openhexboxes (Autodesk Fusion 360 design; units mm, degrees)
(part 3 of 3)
sketch "Skizze22" plane through (0, 0, 0.3) normal (0, 0, -1) x axis (-1, 0, 0)
  line L1 (62.5498, -172.3991) -> (57.5498, -172.3991)
  line L2 (62.5498, -177.3991) -> (62.5498, -172.3991)
  line L3 (57.5498, -177.3991) -> (62.5498, -177.3991)
  line L4 (57.5498, -172.3991) -> (57.5498, -177.3991)
  line L5 (22.7498, -207.1991) -> (22.7498, -212.1991)
  line L6 (22.7498, -212.1991) -> (27.7498, -212.1991)
  line L7 (27.7498, -212.1991) -> (27.7498, -207.1991)
  line L8 (27.7498, -207.1991) -> (22.7498, -207.1991)
  line L9 (28.5498, -207.1991) -> (28.5498, -212.1991)
  line L10 (28.5498, -212.1991) -> (33.5498, -212.1991)
  line L11 (33.5498, -212.1991) -> (33.5498, -207.1991)
  line L12 (33.5498, -207.1991) -> (28.5498, -207.1991)
  line L13 (34.3498, -207.1991) -> (34.3498, -212.1991)
  line L14 (34.3498, -212.1991) -> (39.3498, -212.1991)
  line L15 (39.3498, -212.1991) -> (39.3498, -207.1991)
  line L16 (39.3498, -207.1991) -> (34.3498, -207.1991)
  line L17 (40.1498, -207.1991) -> (40.1498, -212.1991)
  line L18 (40.1498, -212.1991) -> (45.1498, -212.1991)
  line L19 (45.1498, -212.1991) -> (45.1498, -207.1991)
  line L20 (45.1498, -207.1991) -> (40.1498, -207.1991)
  line L21 (45.9498, -207.1991) -> (45.9498, -212.1991)
  line L22 (45.9498, -212.1991) -> (50.9498, -212.1991)
  line L23 (50.9498, -212.1991) -> (50.9498, -207.1991)
  line L24 (50.9498, -207.1991) -> (45.9498, -207.1991)
  line L25 (51.7498, -207.1991) -> (51.7498, -212.1991)
  line L26 (51.7498, -212.1991) -> (56.7498, -212.1991)
  line L27 (56.7498, -212.1991) -> (56.7498, -207.1991)
  line L28 (56.7498, -207.1991) -> (51.7498, -207.1991)
  line L29 (57.5498, -207.1991) -> (57.5498, -212.1991)
  line L30 (57.5498, -212.1991) -> (62.5498, -212.1991)
  line L31 (62.5498, -212.1991) -> (62.5498, -207.1991)
  line L32 (62.5498, -207.1991) -> (57.5498, -207.1991)
  line L33 (63.3498, -207.1991) -> (63.3498, -212.1991)
  line L34 (63.3498, -212.1991) -> (68.3498, -212.1991)
  line L35 (68.3498, -212.1991) -> (68.3498, -207.1991)
  line L36 (68.3498, -207.1991) -> (63.3498, -207.1991)
  line L37 (69.1498, -207.1991) -> (69.1498, -212.1991)
  line L38 (69.1498, -212.1991) -> (74.1498, -212.1991)
  line L39 (74.1498, -212.1991) -> (74.1498, -207.1991)
  line L40 (74.1498, -207.1991) -> (69.1498, -207.1991)
  line L41 (74.9498, -207.1991) -> (74.9498, -212.1991)
  line L42 (74.9498, -212.1991) -> (79.9498, -212.1991)
  line L43 (79.9498, -212.1991) -> (79.9498, -207.1991)
  line L44 (79.9498, -207.1991) -> (74.9498, -207.1991)
  line L45 (80.7498, -207.1991) -> (80.7498, -212.1991)
  line L46 (80.7498, -212.1991) -> (85.7498, -212.1991)
  line L47 (85.7498, -212.1991) -> (85.7498, -207.1991)
  line L48 (85.7498, -207.1991) -> (80.7498, -207.1991)
  line L49 (86.5498, -207.1991) -> (86.5498, -212.1991)
  line L50 (86.5498, -212.1991) -> (91.5498, -212.1991)
  line L51 (91.5498, -212.1991) -> (91.5498, -207.1991)
  line L52 (91.5498, -207.1991) -> (86.5498, -207.1991)
  line L53 (92.3498, -207.1991) -> (92.3498, -212.1991)
  line L54 (92.3498, -212.1991) -> (97.3498, -212.1991)
  line L55 (97.3498, -212.1991) -> (97.3498, -207.1991)
  line L56 (97.3498, -207.1991) -> (92.3498, -207.1991)
  line L57 (98.1498, -207.1991) -> (98.1498, -212.1991)
  line L58 (98.1498, -212.1991) -> (103.1498, -212.1991)
  line L59 (103.1498, -212.1991) -> (103.1498, -207.1991)
  line L60 (103.1498, -207.1991) -> (98.1498, -207.1991)
  line L61 (22.7498, -201.3991) -> (22.7498, -206.3991)
  line L62 (22.7498, -206.3991) -> (27.7498, -206.3991)
  line L63 (27.7498, -206.3991) -> (27.7498, -201.3991)
  line L64 (27.7498, -201.3991) -> (22.7498, -201.3991)
  line L65 (28.5498, -201.3991) -> (28.5498, -206.3991)
  line L66 (28.5498, -206.3991) -> (33.5498, -206.3991)
  line L67 (33.5498, -206.3991) -> (33.5498, -201.3991)
  line L68 (33.5498, -201.3991) -> (28.5498, -201.3991)
  line L69 (34.3498, -201.3991) -> (34.3498, -206.3991)
  line L70 (34.3498, -206.3991) -> (39.3498, -206.3991)
  line L71 (39.3498, -206.3991) -> (39.3498, -201.3991)
  line L72 (39.3498, -201.3991) -> (34.3498, -201.3991)
  line L73 (40.1498, -201.3991) -> (40.1498, -206.3991)
  line L74 (40.1498, -206.3991) -> (45.1498, -206.3991)
  line L75 (45.1498, -206.3991) -> (45.1498, -201.3991)
  line L76 (45.1498, -201.3991) -> (40.1498, -201.3991)
  line L77 (45.9498, -201.3991) -> (45.9498, -206.3991)
  line L78 (45.9498, -206.3991) -> (50.9498, -206.3991)
  line L79 (50.9498, -206.3991) -> (50.9498, -201.3991)
  line L80 (50.9498, -201.3991) -> (45.9498, -201.3991)
  line L81 (51.7498, -201.3991) -> (51.7498, -206.3991)
  line L82 (51.7498, -206.3991) -> (56.7498, -206.3991)
  line L83 (56.7498, -206.3991) -> (56.7498, -201.3991)
  line L84 (56.7498, -201.3991) -> (51.7498, -201.3991)
  line L85 (57.5498, -201.3991) -> (57.5498, -206.3991)
  line L86 (57.5498, -206.3991) -> (62.5498, -206.3991)
  line L87 (62.5498, -206.3991) -> (62.5498, -201.3991)
  line L88 (62.5498, -201.3991) -> (57.5498, -201.3991)
  line L89 (63.3498, -201.3991) -> (63.3498, -206.3991)
  line L90 (63.3498, -206.3991) -> (68.3498, -206.3991)
  line L91 (68.3498, -206.3991) -> (68.3498, -201.3991)
  line L92 (68.3498, -201.3991) -> (63.3498, -201.3991)
  line L93 (69.1498, -201.3991) -> (69.1498, -206.3991)
  line L94 (69.1498, -206.3991) -> (74.1498, -206.3991)
  line L95 (74.1498, -206.3991) -> (74.1498, -201.3991)
  line L96 (74.1498, -201.3991) -> (69.1498, -201.3991)
  line L97 (74.9498, -201.3991) -> (74.9498, -206.3991)
  line L98 (74.9498, -206.3991) -> (79.9498, -206.3991)
  line L99 (79.9498, -206.3991) -> (79.9498, -201.3991)
  line L100 (79.9498, -201.3991) -> (74.9498, -201.3991)
  line L101 (80.7498, -201.3991) -> (80.7498, -206.3991)
  line L102 (80.7498, -206.3991) -> (85.7498, -206.3991)
  line L103 (85.7498, -206.3991) -> (85.7498, -201.3991)
  line L104 (85.7498, -201.3991) -> (80.7498, -201.3991)
  line L105 (86.5498, -201.3991) -> (86.5498, -206.3991)
  line L106 (86.5498, -206.3991) -> (91.5498, -206.3991)
  line L107 (91.5498, -206.3991) -> (91.5498, -201.3991)
  line L108 (91.5498, -201.3991) -> (86.5498, -201.3991)
  line L109 (92.3498, -201.3991) -> (92.3498, -206.3991)
  line L110 (92.3498, -206.3991) -> (97.3498, -206.3991)
  line L111 (97.3498, -206.3991) -> (97.3498, -201.3991)
  line L112 (97.3498, -201.3991) -> (92.3498, -201.3991)
  line L113 (98.1498, -201.3991) -> (98.1498, -206.3991)
  line L114 (98.1498, -206.3991) -> (103.1498, -206.3991)
  line L115 (103.1498, -206.3991) -> (103.1498, -201.3991)
  line L116 (103.1498, -201.3991) -> (98.1498, -201.3991)
  line L117 (22.7498, -195.5991) -> (22.7498, -200.5991)
  line L118 (22.7498, -200.5991) -> (27.7498, -200.5991)
  line L119 (27.7498, -200.5991) -> (27.7498, -195.5991)
  line L120 (27.7498, -195.5991) -> (22.7498, -195.5991)
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  point P2 (57.5498, -172.3991)
  point P3 (62.5498, -172.3991)
  point P5 (57.5498, -177.3991)
  dimension "d102" distance P2 P3 = 5
  dimension "d103" distance P2 P5 = 5
  dimension "d108" distance = 4.3915
  dimension "d106" R-Pattern1-uDistance = 5.8
  dimension "d107" R-Pattern1-vDistance = 5.8
sketch "Skizze23"
extrude "Extrusion19" new body sketch "Skizze22" along normal blind 0.3 bodies "small parts"
extrude "Extrusion20" of existing geometry blind 0.3
copy_paste_bodies "Körper kopieren/einfügen8"
move "Verschieben9"
combine "Kombinieren2" bodies "small parts"
sketch "Skizze24" plane through (-57.5498, 0, 0) normal (-1, 0, 0) x axis (0, 0, 1)
  line L1 (0.3, -178.1991) -> (0.3, -183.1991)
  line L2 (0, -178.1991) -> (0.3, -178.1991)
  line L3 (0, -183.1991) -> (0, -178.1991)
  line L4 (0.3, -183.1991) -> (0, -183.1991)
copy_paste_bodies "Körper kopieren/einfügen7"
move "Verschieben8"
copy_paste_bodies "Körper kopieren/einfügen9"
move "Verschieben10"
copy_paste_bodies "Körper kopieren/einfügen10"
move "Verschieben11"
extrude "Extrusion21" of existing geometry blind 9 second side blind 0.3 bodies "grit_for_easy_detach_substraction body"
extrude "Extrusion22" new body of existing geometry blind -0.3
move "Verschieben12"
combine "Kombinieren3"
copy_paste_bodies "Körper kopieren/einfügen11"
move "Verschieben13"
combine "Kombinieren4" bodies "grit_for_easy_detach_substraction body (1)"
copy_paste_bodies "Körper kopieren/einfügen12"
move "Verschieben14"
extrude "Extrusion23" of existing geometry blind -20
sketch "Skizze25" plane through (0, 0, 10) normal (0, 0, 1) x axis (1, 0, 0)
  line L1 (-23.6181, -323.2077) -> (-22.5788, -323.2077)
  line L2 (-20.4382, -315) -> (-24.3975, -321.8577)
  line L3 (-24.3975, -308.1423) -> (-20.4382, -315)
  line L4 (-25.7831, -309.0423) -> (-25.2635, -308.1423)
  line L5 (-33.342, -298.65) -> (-27.342, -309.0423)
  line L6 (-28.0592, -297.3) -> (-32.5626, -297.3)
  line L7 (-33.6262, -286.1577) -> (-27.6262, -296.55)
  line L8 (-35.0119, -287.0577) -> (-34.4922, -286.1577)
  line L9 (-40.53, -280.2) -> (-36.5707, -287.0577)
  line L10 (-48.4486, -280.2) -> (-40.53, -280.2)
  line L11 (-48.362, -281.85) -> (-48.8816, -280.95)
  line L12 (-61.1414, -283.2) -> (-49.1414, -283.2)
  line L13 (-59.6692, -277.95) -> (-61.9208, -281.85)
  line L14 (-72.1022, -277.2) -> (-60.1022, -277.2)
  line L15 (-72.0156, -278.85) -> (-72.5352, -277.95)
  line L16 (-80.7136, -280.2) -> (-72.795, -280.2)
  line L17 (-84.6729, -287.0577) -> (-80.7136, -280.2)
  line L18 (-83.2006, -287.8077) -> (-84.2398, -287.8077)
  line L19 (-88.4212, -299.55) -> (-82.4212, -289.1577)
  line L20 (-92.2317, -295.65) -> (-89.98, -299.55)
  line L21 (-99.0977, -306.0423) -> (-93.0977, -295.65)
  line L22 (-97.6255, -306.7923) -> (-98.6647, -306.7923)
  line L23 (-100.8054, -315) -> (-96.8461, -308.1423)
  line L24 (-96.8461, -321.8577) -> (-100.8054, -315)
  line L25 (-95.4604, -320.9577) -> (-95.98, -321.8577)
  line L26 (-87.9016, -331.35) -> (-93.9016, -320.9577)
  line L27 (-93.1843, -332.7) -> (-88.681, -332.7)
  line L28 (-87.6173, -343.8423) -> (-93.6173, -333.45)
  line L29 (-86.2317, -342.9423) -> (-86.7513, -343.8423)
  line L30 (-80.7136, -349.8) -> (-84.6729, -342.9423)
  line L31 (-72.795, -349.8) -> (-80.7136, -349.8)
  line L32 (-72.8816, -348.15) -> (-72.362, -349.05)
  line L33 (-60.1022, -346.8) -> (-72.1022, -346.8)
  line L34 (-61.5744, -352.05) -> (-59.3227, -348.15)
  line L35 (-49.1414, -352.8) -> (-61.1414, -352.8)
  line L36 (-49.228, -351.15) -> (-48.7084, -352.05)
  line L37 (-40.53, -349.8) -> (-48.4486, -349.8)
  line L38 (-36.5707, -342.9423) -> (-40.53, -349.8)
  line L39 (-38.0429, -342.1923) -> (-37.0037, -342.1923)
  line L40 (-32.8224, -330.45) -> (-38.8224, -340.8423)
  line L41 (-29.0119, -334.35) -> (-31.2635, -330.45)
  line L42 (-22.1458, -323.9577) -> (-28.1458, -334.35)
  line L43 (-61.1414, -352.8) -> (-49.1414, -352.8)
  line L44 (-93.0977, -295.65) -> (-99.0977, -306.0423)
  line L45 (-89.98, -299.55) -> (-92.2317, -295.65)
  line L46 (-82.4212, -289.1577) -> (-88.4212, -299.55)
  line L47 (-84.2398, -287.8077) -> (-83.2006, -287.8077)
  line L48 (-80.7136, -280.2) -> (-84.6729, -287.0577)
  line L49 (-72.795, -280.2) -> (-80.7136, -280.2)
  line L50 (-72.5352, -277.95) -> (-72.0156, -278.85)
  line L51 (-60.1022, -277.2) -> (-72.1022, -277.2)
  line L52 (-61.9208, -281.85) -> (-59.6692, -277.95)
  line L53 (-49.1414, -283.2) -> (-61.1414, -283.2)
  line L54 (-48.8816, -280.95) -> (-48.362, -281.85)
  line L55 (-40.53, -280.2) -> (-48.4486, -280.2)
  line L56 (-36.5707, -287.0577) -> (-40.53, -280.2)
  line L57 (-34.4922, -286.1577) -> (-35.0119, -287.0577)
  line L58 (-27.6262, -296.55) -> (-33.6262, -286.1577)
  line L59 (-32.5626, -297.3) -> (-28.0592, -297.3)
  line L60 (-27.342, -309.0423) -> (-33.342, -298.65)
  line L61 (-25.2635, -308.1423) -> (-25.7831, -309.0423)
  line L62 (-20.4382, -315) -> (-24.3975, -308.1423)
  line L63 (-24.3975, -321.8577) -> (-20.4382, -315)
  line L64 (-22.5788, -323.2077) -> (-23.6181, -323.2077)
  line L65 (-28.1458, -334.35) -> (-22.1458, -323.9577)
  line L66 (-31.2635, -330.45) -> (-29.0119, -334.35)
  line L67 (-38.8224, -340.8423) -> (-32.8224, -330.45)
  line L68 (-37.0037, -342.1923) -> (-38.0429, -342.1923)
  line L69 (-40.53, -349.8) -> (-36.5707, -342.9423)
  line L70 (-48.4486, -349.8) -> (-40.53, -349.8)
  line L71 (-48.7084, -352.05) -> (-49.228, -351.15)
  line L72 (-61.1414, -352.8) -> (-49.1414, -352.8)
  line L73 (-59.3227, -348.15) -> (-61.5744, -352.05)
  line L74 (-72.1022, -346.8) -> (-60.1022, -346.8)
  line L75 (-72.362, -349.05) -> (-72.8816, -348.15)
  line L76 (-80.7136, -349.8) -> (-72.795, -349.8)
  line L77 (-84.6729, -342.9423) -> (-80.7136, -349.8)
  line L78 (-86.7513, -343.8423) -> (-86.2317, -342.9423)
  line L79 (-93.6173, -333.45) -> (-87.6173, -343.8423)
  line L80 (-88.681, -332.7) -> (-93.1843, -332.7)
  line L81 (-93.9016, -320.9577) -> (-87.9016, -331.35)
  line L82 (-95.98, -321.8577) -> (-95.4604, -320.9577)
  line L83 (-100.8054, -315) -> (-96.8461, -321.8577)
  line L84 (-96.8461, -308.1423) -> (-100.8054, -315)
  line L85 (-98.6647, -306.7923) -> (-97.6255, -306.7923)
  arc A1 centre (-23.6181, -322.3077) radius 0.9 clockwise from (-23.6181, -323.2077) to (-24.3975, -321.8577)
  arc A2 centre (-24.8305, -308.3923) radius 0.5 clockwise from (-25.2635, -308.1423) to (-24.3975, -308.1423)
  arc A3 centre (-26.5626, -308.5923) radius 0.9 clockwise from (-25.7831, -309.0423) to (-27.342, -309.0423)
  arc A4 centre (-32.5626, -298.2) radius 0.9 clockwise from (-33.342, -298.65) to (-32.5626, -297.3)
  arc A5 centre (-28.0592, -296.8) radius 0.5 clockwise from (-27.6262, -296.55) to (-28.0592, -297.3)
  arc A6 centre (-34.0592, -286.4077) radius 0.5 clockwise from (-34.4922, -286.1577) to (-33.6262, -286.1577)
  arc A7 centre (-35.7913, -286.6077) radius 0.9 clockwise from (-35.0119, -287.0577) to (-36.5707, -287.0577)
  arc A8 centre (-48.4486, -280.7) radius 0.5 clockwise from (-48.8816, -280.95) to (-48.4486, -280.2)
  arc A9 centre (-49.1414, -282.3) radius 0.9 clockwise from (-48.362, -281.85) to (-49.1414, -283.2)
  arc A10 centre (-61.1414, -282.3) radius 0.9 clockwise from (-61.1414, -283.2) to (-61.9208, -281.85)
  arc A11 centre (-60.1022, -277.7) radius 0.5 clockwise from (-60.1022, -277.2) to (-59.6692, -277.95)
  arc A12 centre (-72.1022, -277.7) radius 0.5 clockwise from (-72.5352, -277.95) to (-72.1022, -277.2)
  arc A13 centre (-72.795, -279.3) radius 0.9 clockwise from (-72.0156, -278.85) to (-72.795, -280.2)
  arc A14 centre (-84.2398, -287.3077) radius 0.5 clockwise from (-84.2398, -287.8077) to (-84.6729, -287.0577)
  arc A15 centre (-83.2006, -288.7077) radius 0.9 clockwise from (-83.2006, -287.8077) to (-82.4212, -289.1577)
  arc A16 centre (-89.2006, -299.1) radius 0.9 clockwise from (-88.4212, -299.55) to (-89.98, -299.55)
  arc A17 centre (-92.6647, -295.9) radius 0.5 clockwise from (-93.0977, -295.65) to (-92.2317, -295.65)
  arc A18 centre (-98.6647, -306.2923) radius 0.5 clockwise from (-98.6647, -306.7923) to (-99.0977, -306.0423)
  arc A19 centre (-97.6255, -307.6923) radius 0.9 clockwise from (-97.6255, -306.7923) to (-96.8461, -308.1423)
  arc A20 centre (-96.4131, -321.6077) radius 0.5 clockwise from (-95.98, -321.8577) to (-96.8461, -321.8577)
  arc A21 centre (-94.681, -321.4077) radius 0.9 clockwise from (-95.4604, -320.9577) to (-93.9016, -320.9577)
  arc A22 centre (-88.681, -331.8) radius 0.9 clockwise from (-87.9016, -331.35) to (-88.681, -332.7)
  arc A23 centre (-93.1843, -333.2) radius 0.5 clockwise from (-93.6173, -333.45) to (-93.1843, -332.7)
  arc A24 centre (-87.1843, -343.5923) radius 0.5 clockwise from (-86.7513, -343.8423) to (-87.6173, -343.8423)
  arc A25 centre (-85.4523, -343.3923) radius 0.9 clockwise from (-86.2317, -342.9423) to (-84.6729, -342.9423)
  arc A26 centre (-72.795, -349.3) radius 0.5 clockwise from (-72.362, -349.05) to (-72.795, -349.8)
  arc A27 centre (-72.1022, -347.7) radius 0.9 clockwise from (-72.8816, -348.15) to (-72.1022, -346.8)
  arc A28 centre (-60.1022, -347.7) radius 0.9 clockwise from (-60.1022, -346.8) to (-59.3227, -348.15)
  arc A29 centre (-61.1414, -352.3) radius 0.5 clockwise from (-61.1414, -352.8) to (-61.5744, -352.05)
  arc A30 centre (-49.1414, -352.3) radius 0.5 clockwise from (-48.7084, -352.05) to (-49.1414, -352.8)
  arc A31 centre (-48.4486, -350.7) radius 0.9 clockwise from (-49.228, -351.15) to (-48.4486, -349.8)
  arc A32 centre (-37.0037, -342.6923) radius 0.5 clockwise from (-37.0037, -342.1923) to (-36.5707, -342.9423)
  arc A33 centre (-38.0429, -341.2923) radius 0.9 clockwise from (-38.0429, -342.1923) to (-38.8224, -340.8423)
  arc A34 centre (-32.0429, -330.9) radius 0.9 clockwise from (-32.8224, -330.45) to (-31.2635, -330.45)
  arc A35 centre (-28.5788, -334.1) radius 0.5 clockwise from (-28.1458, -334.35) to (-29.0119, -334.35)
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sketch "Skizze26" plane through (0, 0, 10) normal (0, 0, 1) x axis (1, 0, 0)
  line L1 (-64.6632, -315) -> (-62.6425, -311.5)
  line L2 (-62.6425, -318.5) -> (-64.6632, -315)
  line L3 (-58.6011, -318.5) -> (-62.6425, -318.5)
  line L4 (-56.5803, -315) -> (-58.6011, -318.5)
  line L5 (-58.6011, -311.5) -> (-56.5803, -315)
  line L6 (-62.6425, -311.5) -> (-58.6011, -311.5)
  line L7 (-40.53, -280.2) -> (-80.7136, -349.8)
  line L8 (-40.53, -349.8) -> (-80.7136, -280.2)
  line L9 (-20.4382, -315) -> (-60.6218, -315)
  line L10 (-60.6218, -315) -> (-60.6218, -297.0637)
  line L11 (-58.6011, -311.5) -> (-64.6632, -315)
  line L12 (-93.0977, -295.65) -> (-99.0977, -306.0423)
  line L13 (-89.98, -299.55) -> (-92.2317, -295.65)
  line L14 (-82.4212, -289.1577) -> (-88.4212, -299.55)
  line L15 (-84.2398, -287.8077) -> (-83.2006, -287.8077)
  line L16 (-80.7136, -280.2) -> (-84.6729, -287.0577)
  line L17 (-72.795, -280.2) -> (-80.7136, -280.2)
  line L18 (-72.5352, -277.95) -> (-72.0156, -278.85)
  line L19 (-60.1022, -277.2) -> (-72.1022, -277.2)
  line L20 (-61.9208, -281.85) -> (-59.6692, -277.95)
  line L21 (-49.1414, -283.2) -> (-61.1414, -283.2)
  line L22 (-48.8816, -280.95) -> (-48.362, -281.85)
  line L23 (-40.53, -280.2) -> (-48.4486, -280.2)
  line L24 (-36.5707, -287.0577) -> (-40.53, -280.2)
  line L25 (-34.4922, -286.1577) -> (-35.0119, -287.0577)
  line L26 (-27.6262, -296.55) -> (-33.6262, -286.1577)
  line L27 (-32.5626, -297.3) -> (-28.0592, -297.3)
  line L28 (-27.342, -309.0423) -> (-33.342, -298.65)
  line L29 (-25.2635, -308.1423) -> (-25.7831, -309.0423)
  line L30 (-20.4382, -315) -> (-24.3975, -308.1423)
  line L31 (-24.3975, -321.8577) -> (-20.4382, -315)
  line L32 (-22.5788, -323.2077) -> (-23.6181, -323.2077)
  line L33 (-28.1458, -334.35) -> (-22.1458, -323.9577)
  line L34 (-31.2635, -330.45) -> (-29.0119, -334.35)
  line L35 (-38.8224, -340.8423) -> (-32.8224, -330.45)
  line L36 (-37.0037, -342.1923) -> (-38.0429, -342.1923)
  line L37 (-40.53, -349.8) -> (-36.5707, -342.9423)
  line L38 (-48.4486, -349.8) -> (-40.53, -349.8)
  line L39 (-48.7084, -352.05) -> (-49.228, -351.15)
  line L40 (-61.1414, -352.8) -> (-49.1414, -352.8)
  line L41 (-59.3227, -348.15) -> (-61.5744, -352.05)
  line L42 (-72.1022, -346.8) -> (-60.1022, -346.8)
  line L43 (-72.362, -349.05) -> (-72.8816, -348.15)
  line L44 (-80.7136, -349.8) -> (-72.795, -349.8)
  line L45 (-84.6729, -342.9423) -> (-80.7136, -349.8)
  line L46 (-86.7513, -343.8423) -> (-86.2317, -342.9423)
  line L47 (-93.6173, -333.45) -> (-87.6173, -343.8423)
  line L48 (-88.681, -332.7) -> (-93.1843, -332.7)
  line L49 (-93.9016, -320.9577) -> (-87.9016, -331.35)
  line L50 (-95.98, -321.8577) -> (-95.4604, -320.9577)
  line L51 (-100.8054, -315) -> (-96.8461, -321.8577)
  line L52 (-96.8461, -308.1423) -> (-100.8054, -315)
  line L53 (-98.6647, -306.7923) -> (-97.6255, -306.7923)
  line L54 (-40.53, -280.2) -> (-100.8054, -315)
  line L55 (-79.963, -288.5) -> (-81.9837, -285)
  line L56 (-81.9837, -285) -> (-79.963, -281.5)
  line L57 (-79.963, -281.5) -> (-75.9216, -281.5)
  line L58 (-75.9216, -281.5) -> (-73.9008, -285)
  line L59 (-73.9008, -285) -> (-75.9216, -288.5)
  line L60 (-75.9216, -288.5) -> (-79.963, -288.5)
  line L61 (-71.3028, -293.5) -> (-73.3235, -290)
  line L62 (-73.3235, -290) -> (-71.3028, -286.5)
  line L63 (-71.3028, -286.5) -> (-67.2613, -286.5)
  line L64 (-67.2613, -286.5) -> (-65.2406, -290)
  line L65 (-65.2406, -290) -> (-67.2613, -293.5)
  line L66 (-67.2613, -293.5) -> (-71.3028, -293.5)
  line L67 (-79.963, -298.5) -> (-81.9837, -295)
  line L68 (-81.9837, -295) -> (-79.963, -291.5)
  line L69 (-79.963, -291.5) -> (-75.9216, -291.5)
  line L70 (-75.9216, -291.5) -> (-73.9008, -295)
  line L71 (-73.9008, -295) -> (-75.9216, -298.5)
  line L72 (-75.9216, -298.5) -> (-79.963, -298.5)
  line L73 (-45.322, -288.5) -> (-47.3427, -285)
  line L74 (-47.3427, -285) -> (-45.322, -281.5)
  line L75 (-45.322, -281.5) -> (-41.2805, -281.5)
  line L76 (-41.2805, -281.5) -> (-39.2598, -285)
  line L77 (-39.2598, -285) -> (-41.2805, -288.5)
  line L78 (-41.2805, -288.5) -> (-45.322, -288.5)
  line L79 (-53.9823, -293.5) -> (-56.003, -290)
  line L80 (-56.003, -290) -> (-53.9823, -286.5)
  line L81 (-53.9823, -286.5) -> (-49.9408, -286.5)
  line L82 (-49.9408, -286.5) -> (-47.9201, -290)
  line L83 (-47.9201, -290) -> (-49.9408, -293.5)
  line L84 (-49.9408, -293.5) -> (-53.9823, -293.5)
  line L85 (-62.6425, -298.5) -> (-64.6632, -295)
  line L86 (-64.6632, -295) -> (-62.6425, -291.5)
  line L87 (-62.6425, -291.5) -> (-58.6011, -291.5)
  line L88 (-58.6011, -291.5) -> (-56.5803, -295)
  line L89 (-56.5803, -295) -> (-58.6011, -298.5)
  line L90 (-58.6011, -298.5) -> (-62.6425, -298.5)
  line L91 (-71.3028, -303.5) -> (-73.3235, -300)
  line L92 (-73.3235, -300) -> (-71.3028, -296.5)
  line L93 (-71.3028, -296.5) -> (-67.2613, -296.5)
  line L94 (-67.2613, -296.5) -> (-65.2406, -300)
  line L95 (-65.2406, -300) -> (-67.2613, -303.5)
  line L96 (-67.2613, -303.5) -> (-71.3028, -303.5)
  line L97 (-79.963, -308.5) -> (-81.9837, -305)
  line L98 (-81.9837, -305) -> (-79.963, -301.5)
  line L99 (-79.963, -301.5) -> (-75.9216, -301.5)
  line L100 (-75.9216, -301.5) -> (-73.9008, -305)
  line L101 (-73.9008, -305) -> (-75.9216, -308.5)
  line L102 (-75.9216, -308.5) -> (-79.963, -308.5)
  line L103 (-88.6233, -313.5) -> (-90.644, -310)
  line L104 (-90.644, -310) -> (-88.6233, -306.5)
  line L105 (-88.6233, -306.5) -> (-84.5818, -306.5)
  line L106 (-84.5818, -306.5) -> (-82.5611, -310)
  line L107 (-82.5611, -310) -> (-84.5818, -313.5)
  line L108 (-84.5818, -313.5) -> (-88.6233, -313.5)
  line L109 (-97.2835, -318.5) -> (-99.3042, -315)
  line L110 (-99.3042, -315) -> (-97.2835, -311.5)
  line L111 (-97.2835, -311.5) -> (-93.2421, -311.5)
  line L112 (-93.2421, -311.5) -> (-91.2213, -315)
  line L113 (-91.2213, -315) -> (-93.2421, -318.5)
  line L114 (-93.2421, -318.5) -> (-97.2835, -318.5)
  line L115 (-45.322, -298.5) -> (-47.3427, -295)
  line L116 (-47.3427, -295) -> (-45.322, -291.5)
  line L117 (-45.322, -291.5) -> (-41.2805, -291.5)
  line L118 (-41.2805, -291.5) -> (-39.2598, -295)
  line L119 (-39.2598, -295) -> (-41.2805, -298.5)
  line L120 (-41.2805, -298.5) -> (-45.322, -298.5)
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  dimension "d122" distance L3 L6 = 7
  dimension "d125" R-Pattern1-uDistance = 10
  dimension "d126" R-Pattern1-vDistance = 10
extrude "Extrusion24" new body sketch "Skizze26" against normal blind 8
move_face "Fläche verschieben4"
offset_faces "Flächen versetzen6" distance -7.478
move_face "Fläche verschieben5"
combine "Kombinieren5"
extrude "Extrusion25" of existing geometry blind 0.3
extrude "Extrusion26" of existing geometry blind 0.3
copy_paste_bodies "Körper kopieren/einfügen13"
move "Verschieben15"
combine "Kombinieren6" bodies "grit_for_easy_detach_substraction body (1)"
copy_paste_bodies "Körper kopieren/einfügen14"
move "Verschieben16"
move "Verschieben17"
copy_paste_bodies "Körper kopieren/einfügen15"
move "Verschieben18"
combine "Kombinieren7" bodies "grit_for_easy_detach_substraction body (2) (1)"
copy_paste_bodies "Körper kopieren/einfügen16"
move "Verschieben19"
copy_paste_bodies "Körper kopieren/einfügen17"
move "Verschieben20"
combine "Kombinieren8" bodies "grit_for_easy_detach_substraction body (2) (2)"
combine "Kombinieren9" bodies "grit_for_easy_detach_substraction body (2) (3)"
move_face "Fläche verschieben3"
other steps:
base_feature "Basiselement1" bodies "vase_70", "vasemode_50"
base_feature "Basiselement2" bodies "vase_50", "taps"
base_feature "Basiselement3" bodies "vase_50 (1)", "holes 7mm"
base_feature "Basiselement4" bodies "vasemode_50", "vasemode_30"
base_feature "Basiselement5" bodies "vasemode_50 (1)", "holes 13mm"
base_feature "Basiselement6" bodies "vasemode_30", "small parts"
base_feature "Basiselement8" bodies "small parts", "grid"
base_feature "Basiselement7" bodies "vasemode_30 (1)", "easydetach_30mm"
base_feature "Basiselement9" bodies "small parts (1)", "grid_for_easy_detach"
base_feature "Basiselement10" bodies "vasemode_30 (2)"
base_feature "Basiselement11" bodies "grit_for_easy_detach_substraction body", "grit_for_easy_detach_substraction body (1)"
base_feature "Basiselement12" bodies "easydetach_30mm", "bits"
base_feature "Basiselement13" bodies "grit_for_easy_detach_substraction body (1)"
base_feature "Basiselement14" bodies "grit_for_easy_detach_substraction body (2)"
base_feature "Basiselement15" bodies "grit_for_easy_detach_substraction body (2) (1)"
base_feature "Basiselement16" bodies "grit_for_easy_detach_substraction body (2) (2)"
base_feature "Basiselement17" bodies "grit_for_easy_detach_substraction body (2) (3)"
named bodies: "Basis", "vasemode_70", "vase_70", "vasemode_50", "vase_50", "taps", "vase_50 (1)", "holes 7mm", "vasemode_30", "vasemode_50 (1)", "holes 13mm", "small parts", "vasemode_30 (1)", "easydetach_30mm", "grid", "small parts (1)", "grid_for_easy_detach", "vasemode_30 (2)", "grit_for_easy_detach_substraction body", "grit_for_easy_detach_substraction body (1)", "bits", "grit_for_easy_detach_substraction body (2)", "grit_for_easy_detach_substraction body (2) (1)", "grit_for_easy_detach_substraction body (2) (2)", "grit_for_easy_detach_substraction body (2) (3)"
